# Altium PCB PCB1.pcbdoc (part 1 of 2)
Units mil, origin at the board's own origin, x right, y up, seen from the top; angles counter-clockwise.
Board outline 2401.6 x 2401.6 mil, 2 copper layers (Top Layer, Bottom Layer), stack 62.2 mil thick; 61 components, 49 nets, 315 pads, 150 vias.
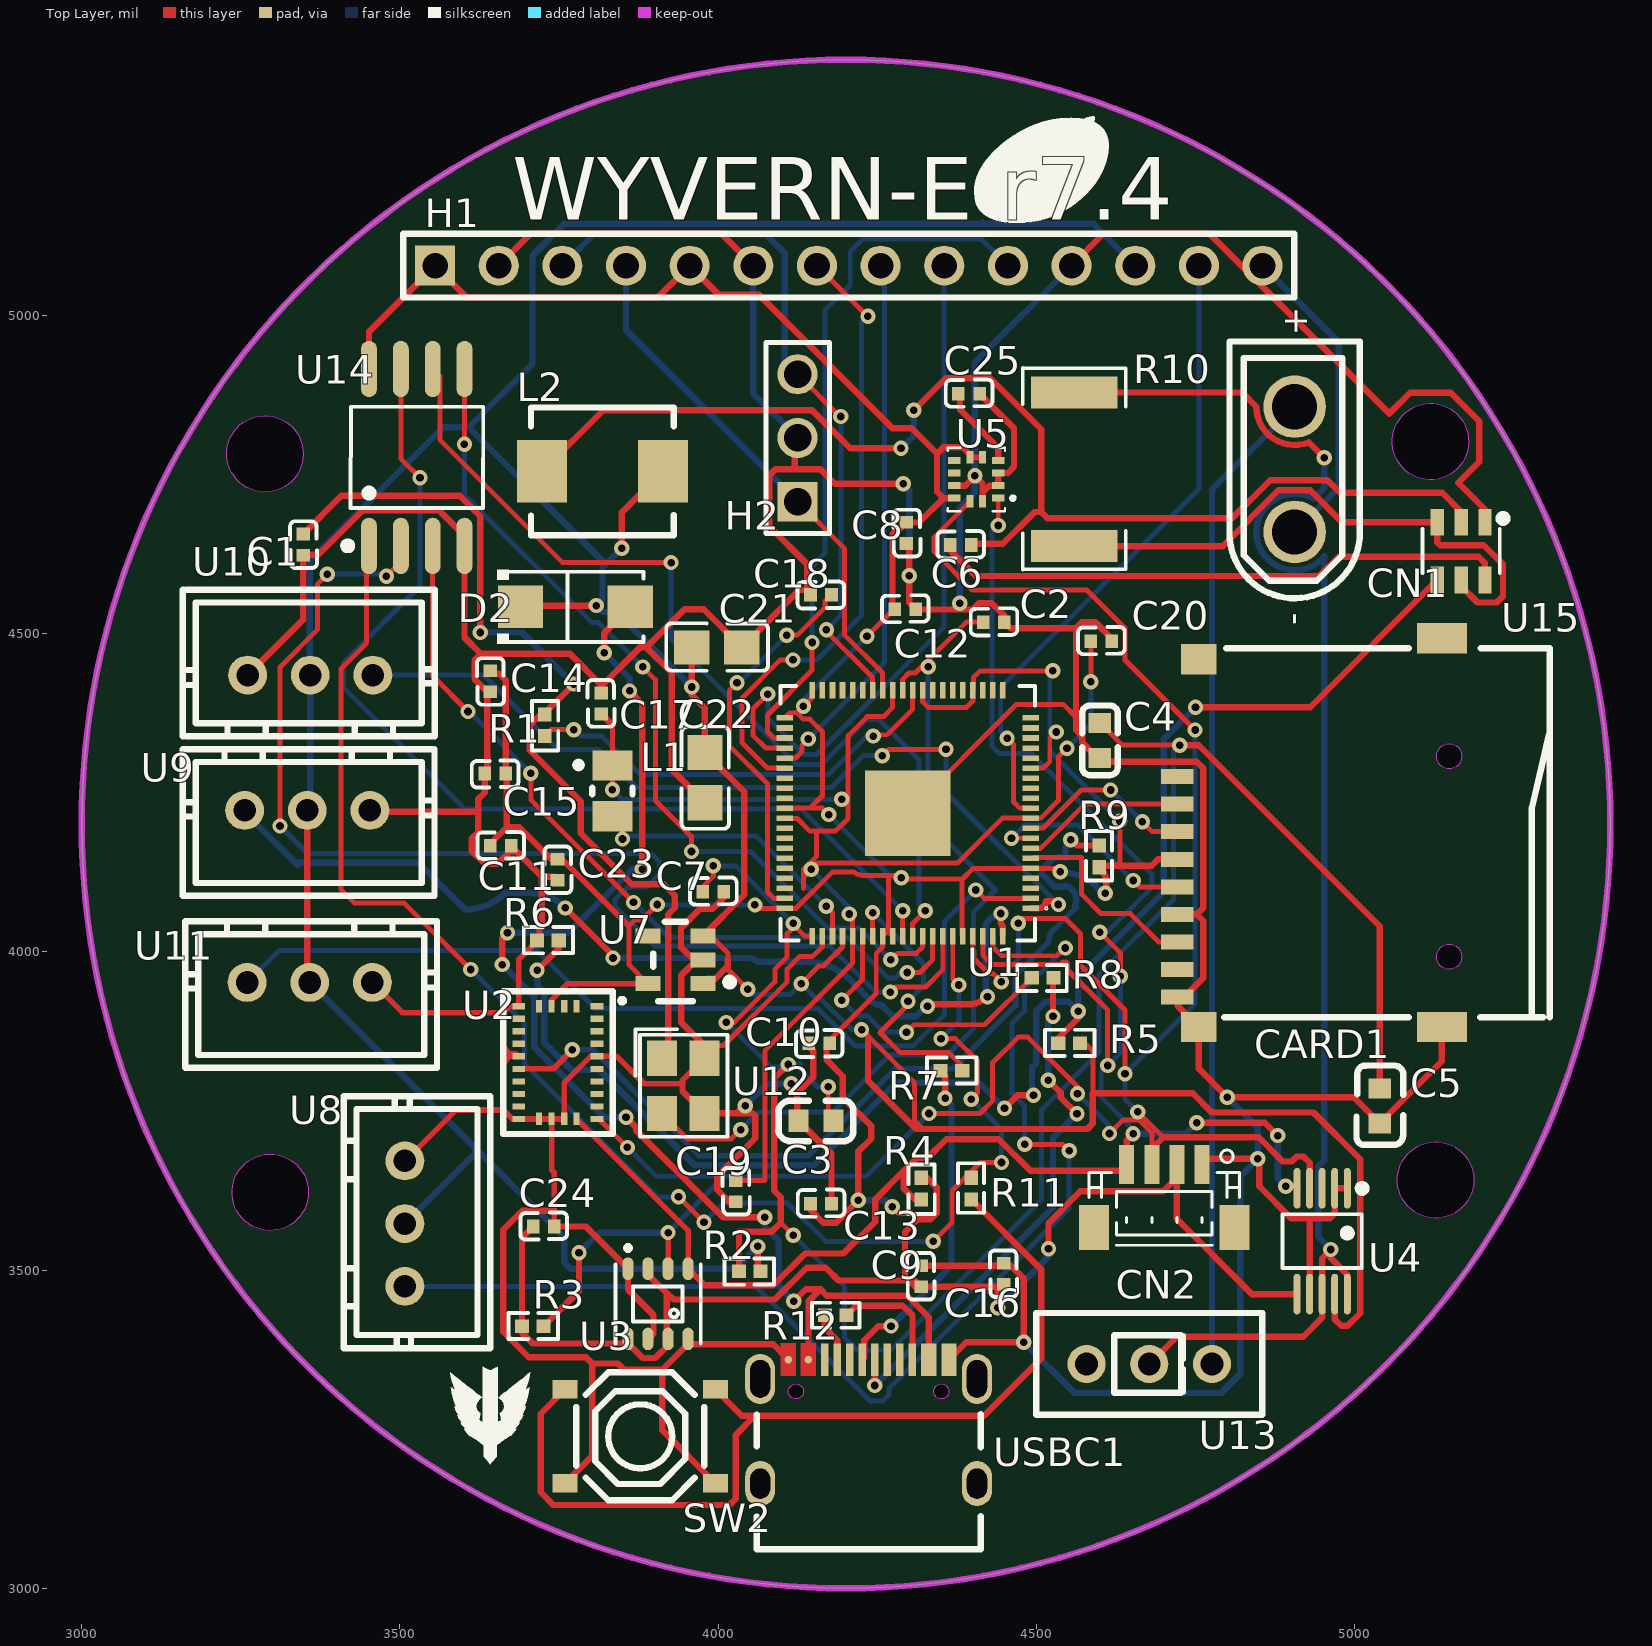
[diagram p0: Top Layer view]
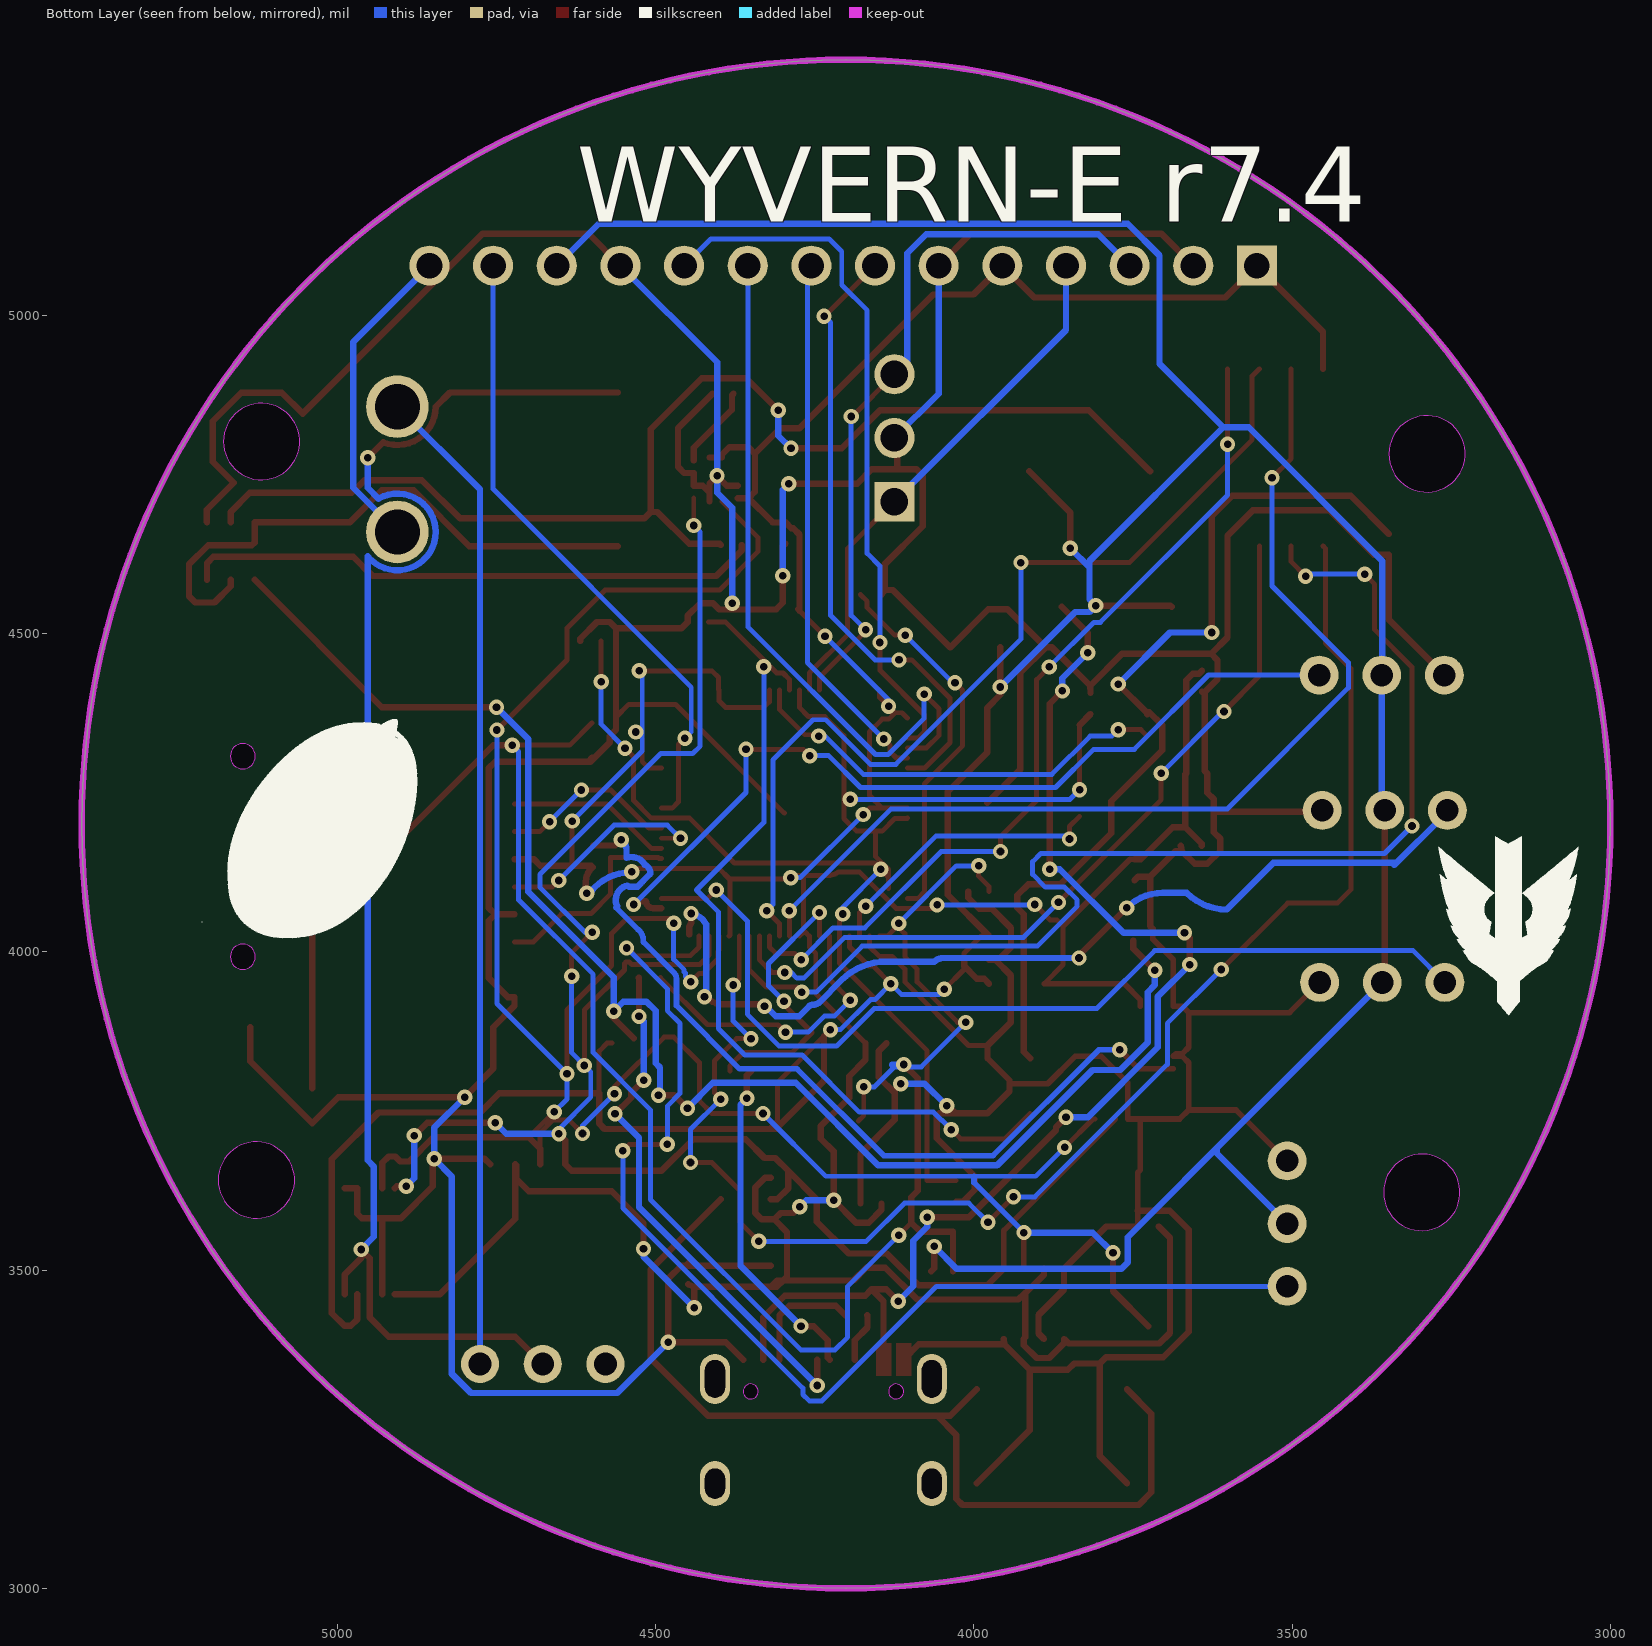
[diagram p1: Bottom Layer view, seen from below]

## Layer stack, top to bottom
Top Solder Mask Layer: solder mask 0.4, Dk 3.3
Top Layer: signal copper 1.4
Dielectric1: surface 59.4, FR4, Dk 4.5
Bottom Layer: signal copper 1.4
Bottom Solder Mask Layer: solder mask 0.4, Dk 3.3

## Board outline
5401.6,4200.8 ccw(c4200.8,4200.8) 3000,4200.8 ccw(c4200.8,4200.8)
cut-out: 3348,4782.3 3347.6,4775.5 3346.5,4768.7 3344.5,4762.1 3341.9,4755.8 3338.5,4749.8 3334.5,4744.3 3329.8,4739.3 3324.7,4734.8 3319,4730.9 3312.9,4727.7 3306.5,4725.2 3299.9,4723.5 3293.1,4722.5 3286.3,4722.3 3279.4,4722.9 3272.7,4724.2 3266.2,4726.4 3260,4729.2 3254.1,4732.7 3248.7,4736.9 3243.8,4741.7 3239.4,4747 3235.7,4752.8 3232.7,4758.9 3230.4,4765.4 3228.8,4772.1 3228,4778.9 3228,4785.7 3228.8,4792.5 3230.4,4799.2 3232.7,4805.7 3235.7,4811.8 3239.4,4817.6 3243.8,4822.9 3248.7,4827.7 3254.1,4831.9 3260,4835.4 3266.2,4838.3 3272.7,4840.4 3279.4,4841.7 3286.3,4842.3 3293.1,4842.1 3299.9,4841.2 3306.5,4839.4 3312.9,4836.9 3319,4833.7 3324.7,4829.9 3329.8,4825.4 3334.5,4820.3 3338.5,4814.8 3341.9,4808.8 3344.5,4802.5 3346.5,4795.9 3347.6,4789.2
cut-out: 5179,4801.7 5178.6,4794.8 5177.4,4788.1 5175.5,4781.5 5172.8,4775.2 5169.4,4769.2 5165.4,4763.7 5160.8,4758.6 5155.6,4754.1 5149.9,4750.2 5143.9,4747 5137.5,4744.6 5130.9,4742.8 5124.1,4741.8 5117.2,4741.6 5110.4,4742.2 5103.7,4743.6 5097.2,4745.7 5090.9,4748.6 5085,4752.1 5079.6,4756.3 5074.7,4761.1 5070.4,4766.4 5066.7,4772.1 5063.6,4778.3 5061.3,4784.7 5059.8,4791.4 5059,4798.2 5059,4805.1 5059.8,4811.9 5061.3,4818.6 5063.6,4825 5066.7,4831.2 5070.4,4837 5074.7,4842.3 5079.6,4847 5085,4851.2 5090.9,4854.8 5097.2,4857.6 5103.7,4859.7 5110.4,4861.1 5117.2,4861.7 5124.1,4861.5 5130.9,4860.5 5137.5,4858.8 5143.9,4856.3 5149.9,4853.1 5155.6,4849.2 5160.8,4844.7 5165.4,4839.7 5169.4,4834.1 5172.8,4828.2 5175.5,4821.8 5177.4,4815.3 5178.6,4808.5
cut-out: 3356.3,3622.1 3355.9,3615.3 3354.7,3608.5 3352.8,3601.9 3350.1,3595.6 3346.7,3589.7 3342.7,3584.1 3338.1,3579.1 3332.9,3574.6 3327.2,3570.7 3321.2,3567.5 3314.8,3565 3308.1,3563.3 3301.4,3562.3 3294.5,3562.1 3287.7,3562.7 3281,3564.1 3274.4,3566.2 3268.2,3569 3262.3,3572.6 3256.9,3576.7 3252,3581.5 3247.6,3586.8 3243.9,3592.6 3240.9,3598.7 3238.6,3605.2 3237.1,3611.9 3236.3,3618.7 3236.3,3625.5 3237.1,3632.4 3238.6,3639 3240.9,3645.5 3243.9,3651.6 3247.6,3657.4 3252,3662.7 3256.9,3667.5 3262.3,3671.7 3268.2,3675.2 3274.4,3678.1 3281,3680.2 3287.7,3681.6 3294.5,3682.1 3301.4,3681.9 3308.1,3681 3314.8,3679.2 3321.2,3676.7 3327.2,3673.5 3332.9,3669.7 3338.1,3665.2 3342.7,3660.1 3346.7,3654.6 3350.1,3648.6 3352.8,3642.3 3354.7,3635.7 3355.9,3629
cut-out: 5187.2,3641.5 5186.8,3634.6 5185.6,3627.9 5183.7,3621.3 5181,3615 5177.7,3609 5173.6,3603.5 5169,3598.4 5163.8,3593.9 5158.2,3590.1 5152.1,3586.9 5145.7,3584.4 5139.1,3582.6 5132.3,3581.6 5125.4,3581.5 5118.6,3582 5111.9,3583.4 5105.4,3585.5 5099.1,3588.4 5093.3,3591.9 5087.8,3596.1 5082.9,3600.9 5078.6,3606.2 5074.9,3611.9 5071.9,3618.1 5069.6,3624.6 5068,3631.2 5067.2,3638 5067.2,3644.9 5068,3651.7 5069.6,3658.4 5071.9,3664.8 5074.9,3671 5078.6,3676.8 5082.9,3682.1 5087.8,3686.8 5093.3,3691 5099.1,3694.6 5105.4,3697.4 5111.9,3699.5 5118.6,3700.9 5125.4,3701.5 5132.3,3701.3 5139.1,3700.3 5145.7,3698.6 5152.1,3696.1 5158.2,3692.9 5163.8,3689 5169,3684.5 5173.6,3679.5 5177.7,3673.9 5181,3668 5183.7,3661.6 5185.6,3655.1 5186.8,3648.3

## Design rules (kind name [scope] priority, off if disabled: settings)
BoardOutlineClearance safeClearance [All] p0: genericclearance=10 ignorepadtopadclearanceinfootprint=FALSE except(0: Arc-SplitContinuation Track-SplitContinuation SMDPad-SplitContinuation THPad-SplitContinuation Via-SplitContinuation Fill-SplitContinuation Poly-SplitContinuation Region-SplitContinuation Text-SplitContinuation)
BoardOutlineClearance otherClearance [All] p0: genericclearance=10 ignorepadtopadclearanceinfootprint=FALSE except(0: Arc-SplitContinuation Track-SplitContinuation SMDPad-SplitContinuation THPad-SplitContinuation Via-SplitContinuation Fill-SplitContinuation Poly-SplitContinuation Region-SplitContinuation Text-SplitContinuation)
Clearance safeClearance [All] p1: gap=7 ignorepadtopadclearanceinfootprint=FALSE
Clearance otherClearance [All] p1: gap=7 ignorepadtopadclearanceinfootprint=FALSE
DiffPairsRouting differentialPair [All] p1: maxuncoupledlength=10 minlimit=6 maxlimit=Infinity mostfreqgap=6 toplayer_minwidth=5 toplayer_prefwidth=10 toplayer_maxwidth=100 bottomlayer_minwidth=5 bottomlayer_prefwidth=10 bottomlayer_maxwidth=100
PasteMaskExpansion pasteMaskExpansion [All] p1: expansion=0
PlaneConnect innerPlane [All] p1: planeconnectstyle=Relief reliefexpansion=20 reliefentries=4 reliefconductorwidth=10 reliefairgap=10
PolygonConnect copperRegion [All] p1: connectstyle=Relief reliefentries=4 reliefconductorwidth=10 polygonreliefangle="90 Angle" airgapwidth=10
RoutingVias viaSize [All] p1: viastyle="Through Hole" holewidth=12.0078 minholewidth=11.811 maxholewidth=236.2204 width=12.0078 minwidth=11.811 maxwidth=236.2204
SolderMaskExpansion solderMaskExpansion [IsVia] p1: useseparateexpansions=TRUE expansion=-1000 expansionbottom=-1000
SolderMaskExpansion solderMaskExpansion [All] p2: useseparateexpansions=TRUE expansion=0.9843 expansionbottom=2.0079
Width trackWidth [All] p1: maxlimit=100 minlimit=5 preferedwidth=10

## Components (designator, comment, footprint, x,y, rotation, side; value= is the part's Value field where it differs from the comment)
C1 "15pF" C0402#1 3347.9,4639.8 r270 top
C2 "15pF" C0402#2 4433.1,4517.8 r0 top
C3 "4.7uF" C0603#1 4153.6,3734.4 r180 top
C4 "4.7uF" C0603#2 4599.8,4332.2 r270 top
C5 "4.7uF" C0603#3 5039.4,3758 r270 top
C6 "100nF" C0402#2 4380.8,4639.1 r0 top
C7 "100nF" C0402#2 3992.3,4094.7 r0 top
C8 "100nF" C0402#2 4295.8,4658.1 r270 top
C9 "100nF" C0402#1 4319,3490.3 r90 top
C10 "100nF" C0402#1 4158.8,3856.4 r180 top
C11 "100nF" C0402#2 3658.2,4166.5 r0 top
C12 "100nF" C0402#1 4293.7,4538.4 r0 top
C13 "100nF" C0402#3 4161.5,3604.4 r0 top
C14 "100nF" C0402#2 3641.6,4424.9 r270 top
C15 "100nF" C0402#2 3649.7,4280.1 r180 top
C16 "100nF" C0402#2 4448.9,3494.2 r90 top
C17 "100nF" C0402#3 3816.6,4390.1 r90 top
C18 "100nF" C0402#3 4161.5,4561.1 r180 top
C19 "100nF" C0402#1 4027.6,3624.1 r270 top
C20 "100nF" C0402#1 4602,4488.2 r0 top
C21 "22uF" C0805#1 3997.7,4478.2 r0 top
C22 "22uF" C0805#2 3979.1,4273.8 r270 top
C23 "100nF" C0402#2 3747.6,4129 r270 top
C24 "100nF" C0402#2 3725.8,3568.5 r0 top
C25 "100nF" C0402#1 4394.1,4877 r0 top
CARD1 "TF-01A" TF-SMD_TF-01A 4929.2,4187.1 r90 top
CN1 "XT30UPB-M" CONN-TH_XT30UPB-M 4905.6,4758 r90 top
CN2 "BM04B-SRSS-TB(LF)(SN)" CONN-SMD_BM04B-SRSS-TB 4700.9,3616.3 r180 top
D2 "SS14" SMA_L4.4-W2.6-LS5.0-RD 3775.5,4541.9 r0 top
H1 "2011-1X14G00SB" HDR-TH_14P-P2.54-V-M_4 4205.2,5078 r0 top
H2 "2.54-1*3P针" HDR-TH_3P-P2.54-V-M-1 4124.8,4807.4 r90 top
L1 "3.3uH" IND-SMD_L2.0-W1.6_AOTA-B201610S3R3-101-T 3833.8,4253 r90 top
L2 "2.2uH" IND-SMD_L5.7-W5.1 3818.1,4754.8 r0 top
R1 "1kΩ" R0402#1 3727.6,4356 r90 top
R2 "33Ω" R0402#1 4049.7,3498.2 r0 top
R3 "10kΩ" R0402#1 3708.7,3411.5 r180 top
R4 "10kΩ" R0402#1 4319,3628.1 r90 top
R5 "56kΩ" R0402#2 4551.3,3856.4 r180 top
R6 "10.2kΩ" R0402#2 3732.4,4017.8 r180 top
R7 "27Ω" R0402#1 4366.2,3813.1 r180 top
R8 "27Ω" R0402#2 4509.5,3959.4 r0 top
R9 "10kΩ" R0402#2 4598.8,4150 r270 top
R10 "10mΩ" R2512 4559.5,4758.1 r270 top
R11 "1kΩ" R0402#2 4397.7,3628.1 r270 top
R12 "5.1kΩ" R0402#1 4184.8,3429.1 r0 top
SW2 "TS-1187A-B-A-B" SW-SMD_4P-L5.1-W5.1-P3.70-LS6.5-TL_H1.5 3877.5,3238.8 r0 top
U1 "RP2350B" QFN-80_L10.0-W10.0-P0.40-TL-EP3.4 4297.7,4217.8 r180 top
U2 "BNO055" LGA-28_L5.2-W3.8-P0.50-BL 3748.1,3825.9 r180 top
U3 "BME680" LGA-8_L3.0-W3.0-P0.80-TR 3905.6,3447 r90 top
U4 "INA226AIDGSR" MSOP-10_L3.0-W3.0-P0.50-LS5.0-BL 4948.9,3545.4 r180 top
U5 "LIS3MDLTR" LGA-12_L2.0-W2.0-P0.50-BL 4405.6,4742.2 r90 top
U7 "AP2112K-3.3TRG1" SOT-23-5_L2.9-W1.6-P0.95-LS2.8-BR 3932.9,3987.4 r0 top
U8 "B3B-XH-A(LF)(SN)" CONN-TH_3P-P2.50_A2501WV2-3P#1 3507.8,3573 r90 top
U9 "B3B-XH-A(LF)(SN)" CONN-TH_3P-P2.50_A2501WV2-3P#2 3354.4,4222.1 r0 top
U10 "B3B-XH-A(LF)(SN)" CONN-TH_3P-P2.50_A2501WV2-3P#2 3359.1,4434.8 r180 top
U11 "B3B-XH-A(LF)(SN)" CONN-TH_3P-P2.50_A2501WV2-3P#3 3358.3,3951.8 r0 top
U12 "12MHz" CRYSTAL-SMD_4P-L3.2-W2.5-BL 3945,3789.5 r270 top
U13 "SS-12D00-G3" SW-TH_3P-L8.8-W3.9-P2.50_SS12D00G3 4677.2,3352.5 r180 top
U14 "W25Q32JVSSIQ" SOIC-8_L5.3-W5.3-P1.27-LS8.0-BL 3526.5,4776.7 r0 top
U15 "TPS564201DDCR" SOT-23-6_L2.9-W1.6-P0.95-LS2.8-BL 5167.3,4629.6 r180 top
USBC1 "TYPE-C-31-M-12" USB-C_SMD-TYPE-C-31-M-12_1 4236.3,3261.9 r0 top

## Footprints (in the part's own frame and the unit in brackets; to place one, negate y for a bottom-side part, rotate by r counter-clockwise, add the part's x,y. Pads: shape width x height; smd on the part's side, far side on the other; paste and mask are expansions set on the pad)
C0402#1 [mil]
  rect 19.7x21.3 smd paste+0 mask+0: 1(-16.6,0) 2(16.5,0)
  silkscreen extent -36,-21 37,22
C0402#2 [mil]
  rect 19.7x21.3 smd paste+0 mask+0: 1(-16.5,0) 2(16.6,0)
  silkscreen extent -36,-21 37,22
C0402#3 [mil]
  rect 19.7x21.3 smd paste+0 mask+0: 1(-16.5,0) 2(16.5,0)
  silkscreen extent -36,-21 37,22
C0603#1 [mil]
  rect 31.5x35.4 smd: 1(-27.6,0) 2(27.5,0)
  silkscreen extent -59,-32 59,32
C0603#2 [mil]
  rect 31.5x35.4 smd paste+0 mask+0: 1(-27.5,0) 2(27.6,0)
  silkscreen extent -55,-28 55,28
C0603#3 [mil]
  rect 31.5x35.4 smd paste+0 mask+0: 1(-27.6,0) 2(27.6,0)
  silkscreen extent -63,-36 61,37
C0805#1 [mil]
  rect 55.5x53.1 smd paste+0 mask+0: 1(-39.4,0) 2(39.4,0)
  silkscreen extent -79,-37 80,38
C0805#2 [mil]
  rect 55.5x55.1 smd paste-3937 mask+2: 1(-39.3,0) 2(39.4,0)
  silkscreen extent -79,-37 81,38
CONN-SMD_BM04B-SRSS-TB [mil]
  rect 47.2x70.9 smd: 0(-110.2,49.7) 0(110.3,49.7)
  rect 23.6x61 smd: 1(-59,-49.7) 2(-19.7,-49.7) 3(19.7,-49.7) 4(59.1,-49.7)
  silkscreen extent -118,-72 118,77
CONN-TH_3P-P2.50_A2501WV2-3P#1 [mil]
  round 61 hole 35.4: 1(-98.5,0) 2(0,0) 3(98.4,0)
  silkscreen extent -196,-134 200,96
CONN-TH_3P-P2.50_A2501WV2-3P#2 [mil]
  round 61 hole 35.4: 1(-98.4,0) 2(0,0) 3(98.4,0)
  silkscreen extent -196,-134 200,96
CONN-TH_3P-P2.50_A2501WV2-3P#3 [mil]
  round 61 hole 35.4: 1(-98.4,0) 2(0.1,0) 3(98.5,0)
  silkscreen extent -196,-134 200,96
CONN-TH_XT30UPB-M [mil]
  round 98.4 hole 70.9: 1(-98.4,0) 2(98.4,0)
  silkscreen extent -202,-102 201,102
CRYSTAL-SMD_4P-L3.2-W2.5-BL [mil]
  rect 55.1x47.2 smd paste+0 mask+0: 1(-43.3,-33.5) 2(43.3,-33.5) 3(43.3,33.4) 4(-43.3,33.4)
  silkscreen extent -89,-75 80,70
HDR-TH_3P-P2.54-V-M-1 [mil]
  rect 62x63 hole 43.3: 1(-100,0)
  round 63 hole 43.3: 2(0,0) 3(100,0)
  silkscreen extent -150,-50 150,50
HDR-TH_14P-P2.54-V-M_4 [mil]
  rect 63x63 hole 40.2: 1(-650,0)
  round 63 hole 40.2: 2(-550,0) 3(-450,0) 4(-350,0) 5(-250,0) 6(-150,0) 7(-50,0) 8(50,0) 9(150,0) 10(250,0) 11(350,0) 12(450,0) 13(550,0) 14(650,0)
  silkscreen extent -700,-50 700,50
IND-SMD_L2.0-W1.6_AOTA-B201610S3R3-101-T [mil]
  rect 47.2x63 smd paste+0 mask+0: 1(-40,0) 2(39.4,0)
  silkscreen extent -6,-32 46,58
IND-SMD_L5.7-W5.1 [mil]
  rect 78.7x98.4 smd paste+0 mask+2: 1(-95,0) 2(95,0)
  silkscreen extent -112,-100 112,100
LGA-8_L3.0-W3.0-P0.80-TR [mil]
  oval 35.4x17.6 smd paste+0 mask+0: 1(55.1,47.2) 2(55.1,15.8) 3(55.1,-15.7) 4(55.1,-47.2) 5(-55.2,-47.2) 6(-55.2,-15.7) 7(-55.2,15.8) 8(-55.2,47.2)
  silkscreen extent -62,-67 92,67
LGA-12_L2.0-W2.0-P0.50-BL [mil]
  rect 11x19.7 smd: 1(-29.5,-34.4) 2(-9.8,-34.4) 3(9.9,-34.4) 4(29.6,-34.4) 7(29.6,34.5) 8(9.9,34.5) 9(-9.8,34.5) 10(-29.5,34.5)
  rect 19.7x11 smd: 5(34.5,-9.8) 6(34.5,9.8) 11(-34.4,9.8) 12(-34.4,-9.8)
  silkscreen extent -50,-60 50,45
LGA-28_L5.2-W3.8-P0.50-BL [mil]
  rect 19.7x9.8 smd: 1(-61.5,-88.6) 6(61.5,-88.6) 7(61.5,-68.9) 8(61.5,-49.2) 9(61.5,-29.6) 10(61.5,-9.9) 11(61.5,9.8) 12(61.5,29.5) 13(61.5,49.2) 14(61.5,68.9) 15(61.5,88.5) 20(-61.5,88.5) 21(-61.5,68.9) 22(-61.5,49.2) 23(-61.5,29.5) 24(-61.5,9.8) 25(-61.5,-9.9) 26(-61.5,-29.6) 27(-61.5,-49.2) 28(-61.5,-68.9)
  rect 9.8x19.7 smd: 2(-29.5,-88.6) 3(-9.9,-88.6) 4(9.8,-88.6) 5(29.5,-88.6) 16(29.5,88.5) 17(9.8,88.5) 18(-9.9,88.5) 19(-29.5,88.5)
  silkscreen extent -105,-112 86,112
MSOP-10_L3.0-W3.0-P0.50-LS5.0-BL [mil]
  oval 11x63.8 smd paste+0 mask+0: 1(-39.4,-83.1) 2(-19.7,-83.1) 3(0,-83.1) 4(19.7,-83.1) 5(39.4,-83.1) 6(39.4,83.1) 7(19.7,83.1) 8(0,83.1) 9(-19.7,83.1) 10(-39.4,83.1)
  silkscreen extent -69,-89 62,42
QFN-80_L10.0-W10.0-P0.40-TL-EP3.4 [mil]
  rect 26.2x8.7 smd: 1(-193.2,149.6) 2(-193.2,133.9) 3(-193.2,118.1) 4(-193.2,102.4) 5(-193.2,86.6) 6(-193.2,70.9) 7(-193.2,55.1) 8(-193.2,39.4) 9(-193.2,23.6) 10(-193.2,7.9) 11(-193.2,-7.8) 12(-193.2,-23.6) 13(-193.2,-39.3) 14(-193.2,-55.1) 15(-193.2,-70.8) 16(-193.2,-86.6) 17(-193.2,-102.3) 18(-193.2,-118.1) 19(-193.2,-133.8) 20(-193.2,-149.6) 41(193.2,-149.6) 42(193.2,-133.8) 43(193.2,-118.1) 44(193.2,-102.3) 45(193.2,-86.6) 46(193.2,-70.8) 47(193.2,-55.1) 48(193.2,-39.3) 49(193.2,-23.6) 50(193.2,-7.8) 51(193.2,7.9) 52(193.2,23.6) 53(193.2,39.4) 54(193.2,55.1) 55(193.2,70.9) 56(193.2,86.6) 57(193.2,102.4) 58(193.2,118.1) 59(193.2,133.9) 60(193.2,149.6)
  rect 8.7x26.2 smd: 21(-149.6,-193.2) 22(-133.8,-193.2) 23(-118.1,-193.2) 24(-102.3,-193.2) 25(-86.6,-193.2) 26(-70.8,-193.2) 27(-55.1,-193.2) 28(-39.3,-193.2) 29(-23.6,-193.2) 30(-7.8,-193.2) 31(7.9,-193.2) 32(23.6,-193.2) 33(39.4,-193.2) 34(55.1,-193.2) 35(70.9,-193.2) 36(86.6,-193.2) 37(102.4,-193.2) 38(118.1,-193.2) 39(133.9,-193.2) 40(149.6,-193.2) 61(149.6,193.2) 62(133.9,193.2) 63(118.1,193.2) 64(102.4,193.2) 65(86.6,193.2) 66(70.9,193.2) 67(55.1,193.2) 68(39.4,193.2) 69(23.6,193.2) 70(7.9,193.2) 71(-7.8,193.2) 72(-23.6,193.2) 73(-39.3,193.2) 74(-55.1,193.2) 75(-70.8,193.2) 76(-86.6,193.2) 77(-102.3,193.2) 78(-118.1,193.2) 79(-133.8,193.2) 80(-149.6,193.2)
  rect 133.9x133.9 smd: 81(0,0)
  silkscreen extent -220,-200 200,200
R0402#1 [mil]
  rect 22.3x21.3 smd paste-3937 mask+0: 1(-17.1,0) 2(17,0)
  silkscreen extent -40,-21 38,20
R0402#2 [mil]
  rect 22.3x21.3 smd paste-3937 mask+0: 1(-17,0) 2(17.1,0)
  silkscreen extent -40,-21 38,20
R2512 [mil]
  rect 50.5x136.1 smd paste-3937 mask+2: 1(-120.7,0) 2(120.8,0)
  silkscreen extent -159,-81 158,81
SMA_L4.4-W2.6-LS5.0-RD [mil]
  rect 70.9x66.9 smd: 1(-86.3,0) 2(86.3,0)
  silkscreen extent -122,-58 107,58
SOIC-8_L5.3-W5.3-P1.27-LS8.0-BL [mil]
  oval 24.8x88.6 smd: 1(-75,-139) 2(-25,-139) 3(25,-139) 4(75,-139) 5(75,139) 6(25,139) 7(-25,139) 8(-75,139)
  silkscreen extent -115,-145 104,80
SOT-23-5_L2.9-W1.6-P0.95-LS2.8-BR [mil]
  rect 39.4x23.6 smd paste+0 mask+2: 1(43.3,-37.4) 2(43.3,0) 3(43.3,37.4) 4(-43.3,37.4) 5(-43.3,-37.4)
  silkscreen extent -35,-65 91,60
SOT-23-6_L2.9-W1.6-P0.95-LS2.8-BL [mil]
  rect 20.9x42.2 smd: 1(-37.4,-45.3) 2(0,-45.3) 3(37.4,-45.3) 4(37.4,45.2) 5(0,45.2) 6(-37.4,45.2)
  silkscreen extent -72,-57 61,35
SW-SMD_4P-L5.1-W5.1-P3.70-LS6.5-TL_H1.5 [mil]
  rect 39.4x29.5 smd: 1(-118.1,73.9) 2(118.1,73.9) 3(-118.1,-73.8) 4(118.1,-73.8)
  silkscreen extent -100,-100 100,100
SW-TH_3P-L8.8-W3.9-P2.50_SS12D00G3 [mil]
  round 60 hole 36 paste+0 mask+2: 1(-98.5,0) 2(0,0) 3(98.4,0)
  silkscreen extent -178,-80 178,80
TF-SMD_TF-01A [mil]
  rect 23.6x51.2 smd: 1(88.2,207.7) 2(44.9,207.7) 3(1.6,207.7) 4(-41.7,207.7) 5(-85,207.7) 6(-128.3,207.7) 7(-171.6,207.7) 8(-214.9,207.7) 9(-258.2,207.7)
  rect 47.2x55.1 smd: 10(-305.5,174.2) 13(272.5,174.2)
  rect 47.2x78.7 smd paste+0 mask+0: 11(-305.5,-207.7) 12(305.5,-207.7)
  Board Outline Layer lines w0.1: -194.9,-199.5 -198.7,-199.8 -202.4,-201 -205.8,-202.8 -208.8,-205.2 -211.2,-208.2 -213,-211.6 -214.2,-215.3 -214.5,-219.1 -214.2,-223 -213,-226.7 -211.2,-230.1 -208.8,-233.1 -205.8,-235.5 -202.4,-237.3 -198.7,-238.5 -194.9,-238.8 -191,-238.5 -187.3,-237.3 -183.9,-235.5 -180.9,-233.1 -178.5,-230.1 -176.7,-226.7 -175.5,-223 -175.2,-219.1 -175.5,-215.3 -176.7,-211.6 -178.5,-208.2 -180.9,-205.2 -183.9,-202.8 -187.3,-201 -191,-199.8 -194.9,-199.5 ; 120.1,-199.5 116.3,-199.8 112.6,-201 109.2,-202.8 106.2,-205.2 103.7,-208.2 101.9,-211.6 100.8,-215.3 100.4,-219.1 100.8,-223 101.9,-226.7 103.7,-230.1 106.2,-233.1 109.2,-235.5 112.6,-237.3 116.3,-238.5 120.1,-238.8 123.9,-238.5 127.6,-237.3 131,-235.5 134,-233.1 136.5,-230.1 138.3,-226.7 139.4,-223 139.8,-219.1 139.4,-215.3 138.3,-211.6 136.5,-208.2 134,-205.2 131,-202.8 127.6,-201 123.9,-199.8 120.1,-199.5
  Board Outline Layer region: -175.2,-219.1 -175.5,-223 -176.7,-226.7 -178.5,-230.1 -180.9,-233.1 -183.9,-235.5 -187.3,-237.3 -191,-238.5 -194.9,-238.8 -198.7,-238.5 -202.4,-237.3 -205.8,-235.5 -208.8,-233.1 -211.2,-230.1 -213,-226.7 -214.2,-223 -214.5,-219.1 -214.2,-215.3 -213,-211.6 -211.2,-208.2 -208.8,-205.2 -205.8,-202.8 -202.4,-201 -198.7,-199.8 -194.9,-199.5 -191,-199.8 -187.3,-201 -183.9,-202.8 -180.9,-205.2 -178.5,-208.2 -176.7,-211.6 -175.5,-215.3
  Board Outline Layer region: -175.2,-219.1 -175.5,-223 -176.7,-226.7 -178.5,-230.1 -180.9,-233.1 -183.9,-235.5 -187.3,-237.3 -191,-238.5 -194.9,-238.8 -198.7,-238.5 -202.4,-237.3 -205.8,-235.5 -208.8,-233.1 -211.2,-230.1 -213,-226.7 -214.2,-223 -214.5,-219.1 -214.2,-215.3 -213,-211.6 -211.2,-208.2 -208.8,-205.2 -205.8,-202.8 -202.4,-201 -198.7,-199.8 -194.9,-199.5 -191,-199.8 -187.3,-201 -183.9,-202.8 -180.9,-205.2 -178.5,-208.2 -176.7,-211.6 -175.5,-215.3
  Board Outline Layer region: 139.8,-219.1 139.4,-223 138.3,-226.7 136.5,-230.1 134,-233.1 131,-235.5 127.6,-237.3 123.9,-238.5 120.1,-238.8 116.3,-238.5 112.6,-237.3 109.2,-235.5 106.2,-233.1 103.7,-230.1 101.9,-226.7 100.8,-223 100.4,-219.1 100.8,-215.3 101.9,-211.6 103.7,-208.2 106.2,-205.2 109.2,-202.8 112.6,-201 116.3,-199.8 120.1,-199.5 123.9,-199.8 127.6,-201 131,-202.8 134,-205.2 136.5,-208.2 138.3,-211.6 139.4,-215.3
  Board Outline Layer region: 139.8,-219.1 139.4,-223 138.3,-226.7 136.5,-230.1 134,-233.1 131,-235.5 127.6,-237.3 123.9,-238.5 120.1,-238.8 116.3,-238.5 112.6,-237.3 109.2,-235.5 106.2,-233.1 103.7,-230.1 101.9,-226.7 100.8,-223 100.4,-219.1 100.8,-215.3 101.9,-211.6 103.7,-208.2 106.2,-205.2 109.2,-202.8 112.6,-201 116.3,-199.8 120.1,-199.5 123.9,-199.8 127.6,-201 131,-202.8 134,-205.2 136.5,-208.2 138.3,-211.6 139.4,-215.3
  Multi-Layer board cut-out: -175.2,-219.1 -175.5,-223 -176.7,-226.7 -178.5,-230.1 -180.9,-233.1 -183.9,-235.5 -187.3,-237.3 -191,-238.5 -194.9,-238.8 -198.7,-238.5 -202.4,-237.3 -205.8,-235.5 -208.8,-233.1 -211.2,-230.1 -213,-226.7 -214.2,-223 -214.5,-219.1 -214.2,-215.3 -213,-211.6 -211.2,-208.2 -208.8,-205.2 -205.8,-202.8 -202.4,-201 -198.7,-199.8 -194.9,-199.5 -191,-199.8 -187.3,-201 -183.9,-202.8 -180.9,-205.2 -178.5,-208.2 -176.7,-211.6 -175.5,-215.3
  Multi-Layer board cut-out: 139.8,-219.1 139.4,-223 138.3,-226.7 136.5,-230.1 134,-233.1 131,-235.5 127.6,-237.3 123.9,-238.5 120.1,-238.8 116.3,-238.5 112.6,-237.3 109.2,-235.5 106.2,-233.1 103.7,-230.1 101.9,-226.7 100.8,-223 100.4,-219.1 100.8,-215.3 101.9,-211.6 103.7,-208.2 106.2,-205.2 109.2,-202.8 112.6,-201 116.3,-199.8 120.1,-199.5 123.9,-199.8 127.6,-201 131,-202.8 134,-205.2 136.5,-208.2 138.3,-211.6 139.4,-215.3
  silkscreen extent -290,-377 290,134
USB-C_SMD-TYPE-C-31-M-12_1 [mil]
  oval 47.2x78.7 hole 31.5 slot 59.1 at 90 deg paste+0 mask+2: 1(170.3,67.2) 4(-170.3,67.2)
  oval 47.2x70.9 hole 31.5 slot 47.2 at 90 deg paste+0 mask+2: 2(170.3,-97.4) 3(-170.3,-97.4)
  round 11.8 smd: A1B12(-126,97.4) A4B9(-94.5,97.4)
  rect 11.8x51.2 smd paste-3937 mask+0: A5(-49.2,97.4) A6(-9.8,97.4) A7(9.8,97.4) A8(49.2,97.4) B5(68.9,97.4) B6(29.5,97.4) B7(-29.5,97.4) B8(-68.9,97.4)
  rect 23.6x51.2 smd paste-3937 mask+0: B1A12(126,97.4) B4A9(94.5,97.4)
  Top Layer region: -114.2,71.8 -126,71.8 -126,71.8 -137.8,71.8 -137.8,123 -126,123 -126,123 -114.2,123
  Top Layer region: -82.7,71.8 -94.5,71.8 -94.5,71.8 -106.3,71.8 -106.3,123 -94.5,123 -94.5,123 -82.7,123
  Board Outline Layer lines w0.1: -125.9,46 -125.2,43.1 -123.7,40.6 -121.7,38.4 -119.2,36.8 -116.4,35.9 -113.4,35.7 -110.5,36.3 -107.8,37.5 -105.6,39.4 -103.8,41.8 -102.7,44.6 -102.4,47.5 -102.7,50.4 -103.8,53.2 -105.6,55.6 -107.8,57.5 -110.5,58.7 -113.4,59.3 -116.4,59.1 -119.2,58.2 -121.7,56.6 -123.7,54.4 -125.2,51.8 -125.9,49 -125.9,46 ; 102.5,46 103.2,43.1 104.6,40.6 106.6,38.4 109.1,36.8 112,35.9 114.9,35.7 117.8,36.3 120.5,37.5 122.8,39.4 124.5,41.8 125.6,44.6 126,47.5 125.6,50.4 124.5,53.2 122.8,55.6 120.5,57.5 117.8,58.7 114.9,59.3 112,59.1 109.1,58.2 106.6,56.6 104.6,54.4 103.2,51.8 102.5,49 102.5,46
  Board Outline Layer region: -102.4,47.5 -102.7,44.6 -103.8,41.8 -105.6,39.4 -107.8,37.5 -110.5,36.3 -113.4,35.7 -116.4,35.9 -119.2,36.8 -121.7,38.4 -123.7,40.6 -125.2,43.1 -125.9,46 -125.9,49 -125.2,51.8 -123.7,54.4 -121.7,56.6 -119.2,58.2 -116.4,59.1 -113.4,59.3 -110.5,58.7 -107.8,57.5 -105.6,55.6 -103.8,53.2 -102.7,50.4
  Board Outline Layer region: -102.4,47.5 -102.7,44.6 -103.8,41.8 -105.6,39.4 -107.8,37.5 -110.5,36.3 -113.4,35.7 -116.4,35.9 -119.2,36.8 -121.7,38.4 -123.7,40.6 -125.2,43.1 -125.9,46 -125.9,49 -125.2,51.8 -123.7,54.4 -121.7,56.6 -119.2,58.2 -116.4,59.1 -113.4,59.3 -110.5,58.7 -107.8,57.5 -105.6,55.6 -103.8,53.2 -102.7,50.4
  Board Outline Layer region: 126,47.5 125.6,44.6 124.5,41.8 122.8,39.4 120.5,37.5 117.8,36.3 114.9,35.7 112,35.9 109.1,36.8 106.6,38.4 104.6,40.6 103.2,43.1 102.5,46 102.5,49 103.2,51.8 104.6,54.4 106.6,56.6 109.1,58.2 112,59.1 114.9,59.3 117.8,58.7 120.5,57.5 122.8,55.6 124.5,53.2 125.6,50.4
  Board Outline Layer region: 126,47.5 125.6,44.6 124.5,41.8 122.8,39.4 120.5,37.5 117.8,36.3 114.9,35.7 112,35.9 109.1,36.8 106.6,38.4 104.6,40.6 103.2,43.1 102.5,46 102.5,49 103.2,51.8 104.6,54.4 106.6,56.6 109.1,58.2 112,59.1 114.9,59.3 117.8,58.7 120.5,57.5 122.8,55.6 124.5,53.2 125.6,50.4
  Multi-Layer board cut-out: -102.4,47.5 -102.7,44.6 -103.8,41.8 -105.6,39.4 -107.8,37.5 -110.5,36.3 -113.4,35.7 -116.4,35.9 -119.2,36.8 -121.7,38.4 -123.7,40.6 -125.2,43.1 -125.9,46 -125.9,49 -125.2,51.8 -123.7,54.4 -121.7,56.6 -119.2,58.2 -116.4,59.1 -113.4,59.3 -110.5,58.7 -107.8,57.5 -105.6,55.6 -103.8,53.2 -102.7,50.4
  Multi-Layer board cut-out: 126,47.5 125.6,44.6 124.5,41.8 122.8,39.4 120.5,37.5 117.8,36.3 114.9,35.7 112,35.9 109.1,36.8 106.6,38.4 104.6,40.6 103.2,43.1 102.5,46 102.5,49 103.2,51.8 104.6,54.4 106.6,56.6 109.1,58.2 112,59.1 114.9,59.3 117.8,58.7 120.5,57.5 122.8,55.6 124.5,53.2 125.6,50.4
  silkscreen extent -176,-200 176,11

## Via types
v1: diameter 24, hole 12, Top Layer to Bottom Layer, 150 vias

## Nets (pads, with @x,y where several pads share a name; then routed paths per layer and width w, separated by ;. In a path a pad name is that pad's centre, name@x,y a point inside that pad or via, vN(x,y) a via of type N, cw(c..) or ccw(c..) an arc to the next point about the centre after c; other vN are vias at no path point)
$1N357: CN2.3 R3.1 U1.77 U2.20 U3.3 U4.4 U5.11 | length 3891.9
  Top Layer w7.8: U2.20@3809.6,3737.4 3812.8,3737.4 v1(3857.4,3692.7) ; v1(4331.2,3746) 4411.2,3746 4431.2,3766 4431.2,3826 4471.2,3866 4486.6,3866 4564.5,3788.1 v1(4564.5,3777.1) ; U5.11@4395.8,4707.8 4339.2,4651.2 4339.2,4628.5 4399.2,4568.5 4579.2,4568.5 4639.2,4508.5 4639.2,4458.5 v1(4749.2,4348.5) ; U1.77@4400,4024.6 4400,4002.7 4402,4000.7 4402,3988.9 4424.7,3966.2 4431.3,3966.2 v1(4444.8,3952.7) ; v1(4471.6,4044.8) 4479.1,4052.4 4545.3,4052.4 4569.2,4028.5 4569.2,3978.5 4639.2,3908.5 v1(4639.2,3808.5) ; v1(4614.8,3714.5) 4636.3,3736 4661.2,3736 4681.2,3716 CN2.3@4681.2,3690.5 ; v1(4659.2,3748.5) 4699.2,3708.5
  Top Layer w8.9: U3.3@3921.3,3502.1 v1(3921.3,3558.9)
  Top Layer w10: R3.1@3725.8,3411.5 3781.3,3467.1 v1(3781.3,3527.1) ; CN2.3@4681.2,3666 4681.2,3690.5 4699.2,3708.5 4849.3,3708.5 4887.2,3670.6 4901.3,3670.6 4909.2,3678.5 4919.2,3678.5 4929.2,3668.5 U4.4@4929.2,3628.5
  Bottom Layer w7.8: v1(3857.4,3692.7) 3902.8,3647.4 3999.8,3647.4 4232.6,3647.4 v1(4331.2,3746) ; v1(4444.8,3952.7) 4452.9,3960.8 4452.9,3966.4 4455.1,3968.5 4455.1,3971.6 4471.6,3988.1 v1(4471.6,4044.8) ; v1(4564.5,3777.1) 4614.8,3726.8 v1(4614.8,3714.5) ; v1(4659.2,3748.5) 4639.2,3768.5 v1(4639.2,3808.5) 4749.2,3918.5 v1(4749.2,4348.5)
  Bottom Layer w8.9: v1(3921.3,3558.9) 3999.8,3637.4 3999.8,3647.4
  Bottom Layer w10: v1(3781.3,3527.1) 3813.1,3558.9 v1(3921.3,3558.9)
$1N359: CN2.4 R4.1 U1.78 U2.19 U3.4 U4.5 U5.1 | length 3190.6
  Top Layer w7.8: U1.78@4415.8,4024.6 4415.8,3994.6 4430.4,3980 4537.4,3980 4541.4,3984 4546.4,3984 4548.9,3981.5 4548.9,3971.5 4611.8,3908.5 v1(4611.8,3821.5) ; v1(4440,4669.7) U5.1@4440,4712.7 ; v1(4599.5,4030.6) 4631.8,3998.3 v1(4631.8,3961.5)
  Top Layer w8.9: U2.19@3777.6,3737.4 3952.8,3562.2 U3.4@3952.8,3502.1
  Top Layer w10: U3.4@3952.8,3502.1 3979,3476 4086.7,3476 4136.7,3526 4196.7,3526 4246.7,3576 4246.7,3610.9 4291.8,3656 ; R4.1@4319,3611 4309,3611 4291.8,3628.2 4291.8,3656 ; v1(4651.8,3714.1) 4641.8,3704.1 CN2.4@4641.8,3666 4631.8,3656 4490.6,3656 4441,3705.6 4358.5,3705.6 4328.9,3676 4311.8,3676 4291.8,3656 ; v1(4751.8,3731.5) 4858.8,3731.5 v1(4879,3711.3) ; v1(4891.8,3631.5) 4906.5,3631.5 U4.5@4909.5,3628.5
  Bottom Layer w7.8: v1(4440,4669.7) 4430,4659.7 4430,4323.2 4441.8,4311.5 4491.8,4311.5 4681.8,4121.5 4681.8,4101.5 4610.9,4030.6 v1(4599.5,4030.6) ; v1(4631.8,3961.5) 4631.8,3841.5 v1(4611.8,3821.5) 4601.8,3811.5 4601.8,3771.5 4651.8,3721.5 v1(4651.8,3714.1)
  Bottom Layer w10: v1(4651.8,3714.1) 4734.4,3714.1 v1(4751.8,3731.5) ; v1(4879,3711.3) 4879,3644.3 v1(4891.8,3631.5)
$1N360: R9.1 U2.11 | length 1367.5
  Top Layer w8.9: U2.11@3686.6,3816.1 3740.8,3816.1 v1(3770.8,3846.1) ; v1(4553.9,4176.2) 4563.1,4167 R9.1@4598.8,4167
  Bottom Layer w8.9: v1(3770.8,3846.1) 3803.6,3846.1 3969.9,3679.8 4141.6,3679.8 4277.9,3816.1 4367.9,3816.1 4467.2,3915.4 4467.2,3957.6 cw(c4481.5,3957.6) 4471.39,3967.71 4519.2,4015.5 ; 4519.2,4015.53 cw(c4541.5,4017.6) 4527.62,4035.18 4562.1,4069.7
  Bottom Layer w10: 4511.6,4132.8 4515.2,4136.3 4516.7,4136.3 cw(c4537.2,4125.9) 4545.63,4147.3 ; 4511.64,4132.76 ccw(c4520.2,4124.2) 4508.1,4124.2 ccw(c4511.8,4124.2) 4509.18,4121.58 4519.2,4111.6 ccw(c4537.2,4125.9) 4522.91,4107.88 4528.4,4102.4 ; 4528,4102.4 4528.4,4102.4 ; 4528.9,4101.9 4528.4,4102.4 ; 4544.24,4103.86 cw(c4540.7,4107.4) 4540.7,4102.4 4528.4,4102.4 ; 4544.32,4103.99 cw(c4539.5,4081.5) 4560.26,4071.6 ; 4545.7,4147.3 4545.7,4161 cw(c4563,4161) v1@4550.77,4173.23 ; v1@4547.6,4174.8 v1@4548.3,4175.5
$1N368: R5.2 R6.1 U15.4 | length 2392.6
  Top Layer w10: v1(3715.5,3971.1) 3749.4,4005.1 R6.1@3749.4,4017.8 ; v1(4449.9,3754.4) 4470.3,3774.8 v1(4495.3,3774.8) ; R5.2@4534.2,3864.3 4565.7,3895.7 v1(4565.7,3906.8) ; v1(4749.9,4384.4) 4929.9,4384.4 U15.4@5129.9,4584.4
  Bottom Layer w10: v1(3715.5,3971.1) 3715.5,3947.8 3726.8,3936.5 3726.8,3857.5 3769.9,3814.4 3813.5,3814.4 3963.5,3664.4 4149.9,3664.4 4279.9,3794.4 4409.9,3794.4 v1(4449.9,3754.4) ; v1(4495.3,3774.8) 4493.1,3777 4493.1,3818.3 4499.9,3825.1 4499.9,3907.2 4514.2,3921.5 4551,3921.5 v1(4565.7,3906.8) 4565.7,3960.2 4699.9,4094.4 4699.9,4334.4 v1(4749.9,4384.4)
$1N370: C6.2 L2.1 U15.2 | length 1938.3
  Top Layer w10: L2.1@3723.1,4754.8 3819.2,4851 4147.3,4851 4207.3,4791 v1(4287.3,4791) ; v1(4307.3,4851) 4357.3,4901 4427.3,4901 4507.3,4821 4507.3,4691 ; C6.2@4397.4,4639.1 4399.3,4641 4447.3,4641 4497.3,4691 4507.3,4691 ; U15.2@5167.3,4674.9 5167.3,4691 5137.3,4721 4977.3,4721 4957.3,4741 4867.3,4741 4807.3,4681 4517.3,4681 4507.3,4691
  Bottom Layer w10: v1(4287.3,4791) 4307.3,4811 v1(4307.3,4851)
$1N371: C6.1 U15.6 | length 908
  Top Layer w10: C6.1@4364.3,4639.1 4364.7,4638.7 4364.7,4630.5 4404.7,4590.5 4944.7,4590.5 4974.7,4620.5 5194.7,4620.5 5204.7,4610.5 U15.6@5204.7,4584.4
$1N373: D2.2 USBC1.A4B9 USBC1.B4A9 | length 1961
  Top Layer w10: v1(3660.8,3979.9) 3660.8,4021.7 v1(3669,4029.9) ; v1(3820.8,4469.9) 3820.8,4500.9 D2.2@3861.8,4541.9 ; v1(3855.2,3740.1) 3870.8,3724.5 3870.8,3719.9 4007.5,3583.2 v1(4073.3,3583.2) ; v1(3860.8,4409.9) 3880.8,4389.9 v1(3880.8,4129.9) ; v1(4118.8,3451) 4137.7,3469.9 4160.8,3469.9 ; USBC1.A4B9@4141.8,3359.3 4141.8,3450.9 4160.8,3469.9 ; USBC1.B4A9@4330.8,3359.3 4330.8,3425.9 4296.8,3459.9 4170.8,3459.9 4160.8,3469.9
  Bottom Layer w10: v1(3660.8,3979.9) 3710.8,3929.9 3710.8,3849.9 3820.6,3740.1 v1(3855.2,3740.1) ; v1(3669,4029.9) 3764.9,4029.9 3864.9,4129.9 v1(3880.8,4129.9) ; v1(3820.8,4469.9) 3860.8,4429.9 v1(3860.8,4409.9) ; v1(4073.3,3583.2) 4073.3,3567.9 4095.1,3546.2 4095.1,3474.7 v1(4118.8,3451)
$1N378: L1.1 U1.63 | length 460.9
  Top Layer w7.8: L1.1@3833.8,4213 3849.6,4197.2 v1(3849.6,4177.2) ; v1(4169.6,4071.6) 4179.6,4061.6 U1.63@4179.6,4024.6
  Bottom Layer w7.8: v1(3849.6,4177.2) 3853.9,4181.6 4059.6,4181.6 v1(4169.6,4071.6)
$1N379: C17.1 C19.1 C20.1 L1.2 U1.10 U1.32 U1.51 U1.65 | length 2322.3
  Top Layer w7.8: v1(3833.8,4254.6) L1.2@3833.8,4292.4 3833.8,4356.4 ; C19.1@4027.6,3640.7 4073.2,3640.7 4073.2,3844.4 4211.1,3982.3 U1.65@4211.1,4024.6 4211.1,4029.5 4211.1,4057 4208.6,4059.5 v1(4206.1,4059.5) ; U1.51@4104.5,4209.9 4104.9,4209.5 4124.1,4209.5 4144.1,4189.5 4184.1,4189.5 4204.1,4209.5 4204.1,4339.5 4234.1,4369.5 4259.6,4369.5 4274.1,4384 U1.32@4274.1,4411 ; 4154.1,4189.5 4154.1,4149.5 4134.1,4129.5 4134.1,4099.5 4134.1,4117.4 v1(4146.1,4129.5) 4156.1,4139.5 4376.1,4139.5 4446.5,4209.9 U1.10@4490.9,4209.9 4506.6,4209.9 4534.7,4238 4534.7,4306.7 v1(4547.9,4319.9) ; v1(4194.1,4239.5) v1@4204.1,4239.5 ; v1(4585.4,4424.2) C20.1@4585.4,4488.2
  Top Layer w10: C17.1@3816.6,4373.6 3833.8,4356.4
  Bottom Layer w7.8: v1(3833.8,4254.6) 3848.9,4239.5 v1(4194.1,4239.5) ; v1(4146.1,4129.5) 4206.1,4069.5 v1(4206.1,4059.5) ; v1(4547.9,4319.9) 4585.4,4357.5 v1(4585.4,4424.2)
$1N380: C3.1 C4.1 C5.1 C7.1 R2.1 U1.61 | length 3394.5
  Top Layer w7.8: C7.1@3975.8,4094.7 3975.8,4102.3 3992.3,4118.8 v1(3992.3,4135.1) ; v1(4012.6,3889.1) 4025.3,3889.1 4088.9,3952.8 4088.9,3972.8 4108.4,3992.3 4108.4,4028.5 v1@4120,4040.1 ; 4098.1,3574.6 v1(4118.1,3554.6) ; v1@4118.1,4040.4 v1(4118.1,4044.6) ; v1@4121.1,4039.6 4136.2,4024.6 U1.61@4148.1,4024.6 ; v1(4172.9,3787.8) 4172.9,3742.7 C3.1@4181.2,3734.4 ; C4.1@4599.8,4359.7 4635,4324.6 v1(4725,4324.6)
  Top Layer w10: R2.1@4032.6,3498.2 4032.6,3560.2 4083.7,3560.2 4098.1,3574.6 4098.1,3614.6 4088.1,3624.6 4088.1,3801.1 v1(4109.9,3822.9) ; v1(4725,4324.6) 4755,4324.6 5039.5,4040.1 C5.1@5039.5,3785.6
  Bottom Layer w7.8: v1(3992.3,4135.1) 4027.5,4135.1 v1(4118.1,4044.6) ; v1(4012.6,3889.1) 4082.5,3819.3 4124.5,3819.3 4155.9,3787.8 v1(4172.9,3787.8) ; v1(4118.1,3554.6) 4198.1,3474.6 4198.1,3394.6 4218.1,3374.6 4271.7,3374.6 4508.1,3610.9 4508.1,3751.7 4598.1,3841.7 4598.1,3964.6 4715,4081.5 4715,4314.6 v1(4725,4324.6)
  Bottom Layer w10: v1(4109.9,3822.9) 4128,3822.9 4128.4,3822.6 4126,3820.1
$1N384: C2.1 U1.31 U12.2 | length 1395.7
  Top Layer w7.8: U12.2@3911.5,3746.2 3951.6,3706.2 4020.8,3706.2 v1(4035.3,3720.6) ; U1.31@4289.8,4411 4289.8,4428 4299.8,4438 4309.8,4438 4389.7,4517.8 C2.1@4416.6,4517.8 ; v1@4319.8,4448 v1(4329.8,4448)
  Bottom Layer w7.8: v1(4035.3,3720.6) 4050.7,3736.1 4051.5,3736.1 4063.4,3748 4179.8,3748 4269.8,3838 4359.8,3838 4401.3,3879.5 4401.3,4062.8 4435.7,4097.2 4329.8,4203.1 v1(4329.8,4448)
$1N387: R7.2 USBC1.A6 | length 530.6
  Top Layer w10: USBC1.A6@4226.5,3359.3 4229.2,3362.1 4229.2,3389.5 4251.7,3412 v1(4271.6,3412) ; R7.2@4349.2,3813.1 4356.5,3805.8 v1(4356.5,3769.9)
  Bottom Layer w10: v1(4271.6,3412) 4366.5,3506.8 4366.5,3759.9 v1(4356.5,3769.9)
$1N388: R8.2 USBC1.A7 | length 834.9
  Top Layer w10: v1(4246.1,3318.7) USBC1.A7@4246.1,3359.3 ; v1(4518.6,3798.2) 4538.2,3778.7 4538.2,3770.9 v1(4563.7,3745.4) ; v1(4526.1,3898.5) 4526.1,3959 R8.2@4526.6,3959.4
  Bottom Layer w10: v1(4246.1,3318.7) 4526.1,3598.7 4526.1,3707.8 v1(4563.7,3745.4) ; v1(4518.6,3798.2) 4518.6,3891 v1(4526.1,3898.5)
$1N391: R7.1 U1.67 | length 445.4
  Top Layer w7.8: U1.67@4242.6,4024.6 v1(4242.6,4061.6) ; v1(4298.3,3922.4) 4292.6,3916.6 4292.6,3911.6 4254.2,3873.2 4285.8,3841.6 4362.6,3841.6 4383.3,3820.9 R7.1@4383.3,3813.1
  Bottom Layer w7.8: v1(4242.6,4061.6) 4322.6,3981.6 4322.6,3946.6 v1(4298.3,3922.4)
$1N392: U1.79 U8.1 | length 1906.9
  Top Layer w7.8: U1.79@4431.5,4024.6 4431.5,4007.6 4445.4,3993.8 4531.6,3993.8 4535.7,3997.8 4537.4,3997.8 v1(4545.5,4005.9) ; v1(4481.5,3697.6) 4541.5,3697.6 v1(4551.5,3687.6)
  Bottom Layer w7.8: U8.1@3507.8,3474.5 4058.5,3474.5 4238.5,3294.5 4258.5,3294.5 4268.5,3304.5 4268.5,3314.5 4551.5,3597.6 v1(4551.5,3687.6) ; v1(4481.5,3697.6) 4481.5,3757.6 4461.5,3777.6 4461.5,3887.6 4481.5,3907.6 4481.5,3941.9 v1(4545.5,4005.9)
$1N393: U1.80 U9.1 | length 1488.3
  Top Layer w10: v1(3759.9,4069) 3831.9,3997 cw(c3825.2,3990.3) v1(3834.7,3990.3) ; v1@4333,3917.4 4393.3,3917.4 ccw(c4393.3,3955.9) v1@4420.52,3928.68 ; 4443.8,4045.3 v1@4443.8,4060.8 ; 4443.85,4045.3 cw(c4435.9,4037.7) 4446.9,4037.7 4446.9,4028.3 ccw(c4448.4,4028.3) U1.80@4447.34,4027.24
  Bottom Layer w10: U9.1@3257.6,4224.9 ccw(c3274.3,4224.9) 3262.49,4213.09 3339.3,4136.3 ; 3339.3,4139.7 3529.3,4139.7 3602.4,4066.5 ccw(c3602.4,4156.1) 3665.65,4092.63 ; 3665.65,4092.73 ccw(c3602.4,4156.2) 3665.76,4092.84 ; 3665.7,4092.6 3702.9,4092.6 ; 3702.9,4092.7 cw(c3702.9,4012) v1@3759.96,4069.06 ; v1(3834.7,3990.3) 4048.6,3990.3 ; 4048.6,3990.2 cw(c4048.6,3971.8) 4061.61,3984.81 ; 4062.1,3984.6 4137.3,3984.6 cw(c4137.3,3884.6) 4208.01,3955.31 4242.3,3921 ; 4242.26,3921.06 ccw(c4252.8,3931.6) 4252.8,3916.7 cw(c4252.8,3907.3) 4259.45,3913.95 ; 4259.4,3913.9 4274.5,3898.8 4311.2,3898.8 v1@4323.1,3910.6 ; v1@4420.4,3930.1 4420.4,4043.2 ; 4420.45,4043.21 cw(c4449.1,4028.3) v1@4444.21,4060.23
  other v1: 4328.9,3914.5 4423.2,3929.6 4444.2,4060.3
$1N394: U1.1 U10.1 | length 1367.8
  Top Layer w7.8: v1(4257.9,4308.2) 4267.9,4318.2 v1(4357.9,4318.2)
  Top Layer w10: U1.1@4490.9,4068.2 U1.1@4493.7,4068.2 ; U1.1@4493.7,4068.1 ccw(c4493.7,4070.9) U1.1@4495.18,4068.53 ; U1.1@4495.2,4068.6 4504,4068.6 ccw(c4504,4079.6) 4515,4079.6 4529.1,4079.6 v1(4534.5,4074.3)
  Bottom Layer w7.8: U10.1@3457.5,4434.8 3631.2,4434.8 3747.9,4318.2 3811.7,4318.2 3871.7,4258.2 4177.9,4258.2 4227.9,4308.2 v1(4257.9,4308.2) ; v1(4357.9,4318.2) 4357.9,4250.4 4534.1,4074.3 v1(4534.5,4074.3)
$1N395: U1.2 U11.1 | length 1506.8
  Top Layer w7.8: v1(4404.7,4097.2) 4418,4083.9 U1.2@4490.9,4083.9
  Bottom Layer w7.8: U11.1@3259.9,3951.8 3309.9,4001.8 3715.8,4001.8 3806.6,3911 4156.6,3911 4215.8,3851.8 4305.8,3851.8 4355.8,3901.9 4355.8,4048.3 v1(4404.7,4097.2)
$1N398: H1.3 H2.3 U1.34 | length 1145.5
  Top Layer w7.8: H2.3@4124.8,4907.4 4191.2,4841 v1(4192.6,4841) ; v1(4170,4506.1) 4170,4503.5 4242.6,4431 U1.34@4242.6,4411
  Bottom Layer w7.8: v1(4170,4506.1) 4192.6,4528.7 v1(4192.6,4841)
  Bottom Layer w10: H1.3@3755.2,5078 3804.6,5127.4 4074.8,5127.4 4104.8,5097.4 4104.8,4927.4 H2.3@4124.8,4907.4
$1N399: H1.4 H2.1 U1.33 | length 834
  Top Layer w7.8: H2.1@4124.8,4707.4 4198.3,4633.9 4198.3,4498 4258.3,4438 U1.33@4258.3,4411
  Bottom Layer w10: H1.4@3855.2,5078 3855.2,4976.9 H2.1@4124.8,4707.4
$1N400: H1.7 U1.46 | length 982.1
  Top Layer w7.8: U1.46@4104.5,4288.6 4077.5,4288.6 4037.5,4328.6 4037.5,4398.6 4097.5,4458.6 v1(4117.5,4458.6) ; H1.7@4155.2,5078 4234.6,4998.6 v1(4235.2,4998.6)
  Bottom Layer w7.8: v1(4117.5,4458.6) 4155.2,4458.6 4225.2,4528.6 4225.2,4988.6 v1(4235.2,4998.6)
$1N401: H1.8 U1.45 | length 851.2
  Top Layer w7.8: U1.45@4104.5,4304.4 4121.5,4304.4 4131.5,4314.4 4131.5,4324.4 v1(4141.5,4334.4)
  Bottom Layer w7.8: v1(4141.5,4334.4) 4261.5,4454.4 4261.5,5071.8 H1.8@4255.2,5078
$1N402: H1.9 U1.44 | length 1122
  Top Layer w7.8: v1(4077.9,4404.9) 4054.5,4381.5 4054.5,4340.1 4074.5,4320.1 U1.44@4104.5,4320.1
  Bottom Layer w7.8: v1(4077.9,4404.9) 4077.9,4366.7 4134.5,4310.1 4154.5,4310.1 4354.5,4510.1 4354.5,5077.2 H1.9@4355.2,5078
